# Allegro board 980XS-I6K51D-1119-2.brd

Outline 581.66 x 429.26 mm; copper layers: TOP, L02_GND, L03_DPS, L04_GND, L05_DPS, L06_GND, L07_DPS, L08_GND, L09_DPS, L10_GND, L11_DPS, L12_GND, L13_SIGNAL, L14_GND, L15_SIGNAL, L16_GND, L17_SIGNAL, L18_GND, L19_SIGNAL, L20_GND, L21_SIGNAL, L22_GND, L23_SIGNAL, L24_GND, L25_SIGNAL, L26_GND, L27_SIGNAL, L28_GND, L29_SIGNAL, L30_GND, L31_SIGNAL, L32_GND, L33_SIGNAL, L34_GND, L35_DPS, L36_UDB, L37_GND, BOTTOM. Coordinates in mm from the lower left corner of the outline.
Outline path: 0,429.26 206.45,429.26 arc(217.17,423.61) 227.89,429.26 353.77,429.26 arc(364.49,423.61) 375.21,429.26 581.66,429.26 581.66,0 301.55,0 arc(290.83,5.65) 280.11,0 0,0 0,429.26

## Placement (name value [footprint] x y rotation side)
BD5  BD120-1.5A-S4-MU  [FB0402]  543.47 239.79 270 bottom
BD9  BD120-1.5A-S4-MU  [FB0402]  224.66 243.83 270 bottom
BD21  BD120-1.5A-S4-MU  [FB0402]  222.95 232.36 0 bottom
BD1721  BD120-1.5A-S4-MU  [FB0402]  543.47 226.84 270 bottom
BD1722  BD120-1.5A-S4-MU  [FB0402]  543.09 213.5 270 bottom
BD1723  BD120-1.5A-S4-MU  [FB0402]  543.09 199.41 270 bottom
BD1728  BD120-1.5A-S4-MU  [FB0402]  245.15 273.73 180 bottom
BDB5  BD120-1.5A-S4-MU  [FB0402]  232.36 264.33 270 bottom
BDB6  BD120-1.5A-S4-MU  [FB0402]  220.55 264.33 270 bottom
BDB7  BD120-1.5A-S4-MU  [FB0402]  211.03 234.89 0 bottom
BDB8  BD120-1.5A-S4-MU  [FB0402]  211.03 246.46 0 bottom
BGA293-9X7-P0.4  REF-CODE-SOCKET  [SOCKET_CODE]  284.21 469.34 0 top
C262  0.1U-16-X7S-S2-MU  [C0201]  224.41 232.06 270 bottom
C264  NC/10U-16-X7R-S8-SS  [C0805]  243.28 276.07 0 bottom
C267  33P-50-N-S2-MU  [C0201]  236.23 224.18 270 bottom
C268  33P-50-N-S2-MU  [C0201]  235.23 224.18 270 bottom
C271  12P-50-N-S4-MU  [C0402]  240.52 270.61 90 bottom
C272  12P-50-N-S4-MU  [C0402]  240.52 272.63 270 bottom
C278  1U-10-X7S-S4-TDK  [C0402]  232.87 293.11 0 bottom
C279  1U-10-X7S-S4-TDK  [C0402]  232.87 291.92 0 bottom
C280  0.1U-16-X-S4-MU  [C0402]  232.87 290.72 0 bottom
C281  0.1U-16-X-S4-MU  [C0402]  232.87 289.53 0 bottom
C282  1U-10-X7S-S4-TDK  [C0402]  238.7 286.48 270 bottom
C283  0.1U-16-X-S4-MU  [C0402]  237.54 286.48 270 bottom
C284  1U-10-X7S-S4-TDK  [C0402]  237.62 297.85 90 bottom
C285  0.1U-16-X-S4-MU  [C0402]  238.81 297.85 90 bottom
C286  0.1U-16-X-S4-MU  [C0402]  233.82 297.35 180 bottom
C288  1000P-50-X7R-S2-MU  [C0201]  233.49 295.57 270 bottom
C289  0.1U-16-X-S4-MU  [C0402]  231.21 294.81 270 bottom
C290  NC/0.1U-16-X7R-S4-TY  [C0402]  224.35 296.03 180 bottom
C298  0.1U-16-X7S-S2-MU  [C0201]  222.95 292.65 90 bottom
C299  0.1U-16-X7S-S2-MU  [C0201]  220.02 296.97 180 bottom
C300  0.1U-16-X-S4-MU  [C0402]  220.67 290.87 270 bottom
C301  1U-10-X7S-S4-TDK  [C0402]  219.51 290.87 270 bottom
C302  10P-50-N-S2-MU  [C0201]  229.27 260.38 270 bottom
C309  10P-50-N-S2-MU  [C0201]  241.08 260.38 270 bottom
C310  10P-50-N-S2-MU  [C0201]  241.08 261.68 90 bottom
C318  10P-50-N-S2-MU  [C0201]  241.08 263.42 270 bottom
C320  10P-50-N-S2-MU  [C0201]  229.27 261.68 90 bottom
C332  2.2U-16-X7R-S6-TY  [C0603]  109.1 226.65 270 bottom
C333  0.1U-16-X-S4-MU  [C0402]  107.7 226.83 270 bottom
C334  10U-16-X7R-S8-SS  [C0805]  100.08 226.53 90 bottom
C335  0.1U-16-X-S4-MU  [C0402]  101.74 226.35 90 bottom
C336  4.7U-25-X7R-S8-TY  [C0805]  87.58 240.29 270 bottom
C337  0.1U-16-X-S4-MU  [C0402]  87.6 237.74 180 bottom
C338  4.7U-25-X7R-S8-TY  [C0805]  106 240.29 270 bottom
C339  0.1U-16-X-S4-MU  [C0402]  106.03 237.74 180 bottom
C400  2.2U-10-X-S4-MU  [C0402]  540.94 239.82 90 bottom
C401  0.1U-16-X-S4-MU  [C0402]  542.2 239.82 90 bottom
C402  4.7U-6.3-X-S4-MU  [C0402]  523.51 152.12 0 bottom
C403  22U-16-X5R-SA-SS  [C1206]  520.12 149.58 90 bottom
C404  10U-25-X-S6-MU  [C0603]  519.86 146.58 180 bottom
C405  1U-10-X7S-S4-TDK  [C0402]  520.37 145.26 180 bottom
C406  0.1U-16-X-S4-MU  [C0402]  90.42 287.53 180 bottom
C407  2.2U-10-X-S4-MU  [C0402]  82.6 288.09 270 bottom
C408  0.1U-16-X-S4-MU  [C0402]  83.74 288.09 270 bottom
C409  0.1U-16-X-S4-MU  [C0402]  73.71 296.14 0 bottom
C410  0.1U-16-X-S4-MU  [C0402]  508.66 225.73 270 bottom
C411  0.1U-16-X-S4-MU  [C0402]  498.63 233.78 0 bottom
C412  2.2U-10-X-S4-MU  [C0402]  507.51 225.73 270 bottom
C413  0.1U-16-X-S4-MU  [C0402]  515.33 225.16 180 bottom
C415  0.1U-16-X-S4-MU  [C0402]  90.42 273.81 180 bottom
C416  2.2U-10-X-S4-MU  [C0402]  82.6 274.38 270 bottom
C417  0.1U-16-X-S4-MU  [C0402]  73.71 282.43 0 bottom
C475  4.7U-6.3-X-S4-MU  [C0402]  256.72 272.09 270 bottom
C476  1U-10-X7S-S4-TDK  [C0402]  249.86 275.23 90 bottom
C477  10U-25-X-S6-MU  [C0603]  251.18 275.74 90 bottom
C478  22U-16-X5R-SA-SS  [C1206]  254.18 275.49 0 bottom
C894  0.1U-16-X-S4-MU  [C0402]  542.2 226.87 90 bottom
C895  2.2U-10-X-S4-MU  [C0402]  540.94 226.87 90 bottom
C910  0.1U-16-X-S4-MU  [C0402]  83.74 274.38 270 bottom
C922  0.1U-16-X-S4-MU  [C0402]  232.36 262.2 270 bottom
C923  0.1U-16-X-S4-MU  [C0402]  220.55 262.2 270 bottom
C924  10P-50-N-S2-MU  [C0201]  229.27 263.42 270 bottom
C955  0.1U-16-X-S4-MU  [C0402]  90.42 260.1 180 bottom
C956  2.2U-10-X-S4-MU  [C0402]  82.6 260.66 270 bottom
C957  0.1U-16-X-S4-MU  [C0402]  73.71 268.71 0 bottom
C958  0.1U-16-X-S4-MU  [C0402]  83.74 260.66 270 bottom
C983  0.1U-16-X-S4-MU  [C0402]  541.82 213.53 90 bottom
C984  2.2U-10-X-S4-MU  [C0402]  540.55 213.53 90 bottom
C985  0.1U-16-X-S4-MU  [C0402]  541.82 199.44 90 bottom
C986  2.2U-10-X-S4-MU  [C0402]  540.55 199.44 90 bottom
C1074  0.1U-16-X7S-S2-MU  [C0201_MINI]  243.6 273.98 90 bottom
C1082  0.1U-16-X-S4-MU  [C0402]  508.66 207.57 270 bottom
C1083  0.1U-16-X-S4-MU  [C0402]  248.15 224.79 0 bottom
C1085  2.2U-10-X-S4-MU  [C0402]  498.63 215.62 0 bottom
C1086  10P-50-N-S2-MU  [C0201]  214.98 255.18 0 bottom
C1087  10P-50-N-S2-MU  [C0201]  213.69 255.18 180 bottom
C1088  10P-50-N-S2-MU  [C0201]  211.94 255.18 0 bottom
C1089  0.1U-16-X-S4-MU  [C0402]  213.16 234.89 0 bottom
C1090  0.1U-16-X-S4-MU  [C0402]  213.16 246.46 0 bottom
C1091  10P-50-N-S2-MU  [C0201]  213.69 243.61 180 bottom
C1093  10P-50-N-S2-MU  [C0201]  214.98 243.61 0 bottom
CA1  0.1U-16-X-S4-MU  [C0402]  205.72 237.49 0 bottom
CA2  10U-25-X7R-SA  [C1206]  205.72 240.03 0 bottom
CA7  10U-25-X7R-SA  [C1206]  245.12 285.5 0 bottom
CA8  0.1U-16-X-S4-MU  [C0402]  245.12 283.46 0 bottom
CA19  470U-25-E-S10.4X10.4  [EC_10P3X10_S]  189.66 230.89 90 bottom
CA20  10U-25-X7R-SA  [C1206]  216.67 285.5 0 bottom
CA21  0.1U-16-X-S4-MU  [C0402]  216.67 283.46 0 bottom
CA22  10U-25-X7R-SA  [C1206]  222.76 281.43 0 bottom
CA23  0.1U-16-X-S4-MU  [C0402]  222.76 279.4 0 bottom
CA24  10U-25-X7R-SA  [C1206]  216.67 281.43 0 bottom
CA25  0.1U-16-X-S4-MU  [C0402]  216.67 279.4 0 bottom
CA26  10U-25-X7R-SA  [C1206]  235.18 281.43 0 bottom
CA27  0.1U-16-X-S4-MU  [C0402]  235.18 279.4 0 bottom
CA34  10U-25-X7R-SA  [C1206]  245.12 281.43 0 bottom
CA35  0.1U-16-X-S4-MU  [C0402]  245.12 279.4 0 bottom
CA36  0.1U-16-X-S4-MU  [C0402]  228.85 279.4 0 bottom
CA37  10U-25-X7R-SA  [C1206]  228.85 281.43 0 bottom
CA38  10U-25-X7R-SA  [C1206]  188.01 283.69 0 top
CA39  0.1U-16-X-S4-MU  [C0402]  206.26 242.54 0 top
CB1  0.1U-25-X-S6  [C0603]  416.81 133.35 0 bottom
CB2  10U-25-X7R-SA  [C1206]  416.81 130.81 0 bottom
CB3  0.1U-25-X-S6  [C0603]  560.07 133.35 0 bottom
CB4  10U-25-X7R-SA  [C1206]  560.07 130.81 0 bottom
CB5  0.1U-25-X-S6  [C0603]  560.07 295.91 180 bottom
CB6  10U-25-X7R-SA  [C1206]  560.07 298.45 180 bottom
CB7  0.1U-25-X-S6  [C0603]  424.16 290.83 180 bottom
CB8  10U-25-X7R-SA  [C1206]  424.16 293.37 180 bottom
CB9  0.1U-25-X-S6  [C0603]  164.85 133.35 0 bottom
CB10  10U-25-X7R-SA  [C1206]  164.85 130.81 0 bottom
CB11  0.1U-25-X-S6  [C0603]  157.46 290.83 180 bottom
CB12  10U-25-X7R-SA  [C1206]  157.46 293.37 180 bottom
CB13  0.1U-25-X-S6  [C0603]  21.59 133.35 0 bottom
CB14  10U-25-X7R-SA  [C1206]  21.59 130.81 0 bottom
CB15  0.1U-25-X-S6  [C0603]  21.59 295.91 180 bottom
CB16  10U-25-X7R-SA  [C1206]  21.59 298.45 180 bottom
CC1  0.1U-16-X7S-S2-MU  [C0201_MINI]  230.19 246.91 180 bottom
CC2  0.1U-16-X7S-S2-MU  [C0201_MINI]  230.5 250.48 90 bottom
CC3  0.1U-16-X7S-S2-MU  [C0201_MINI]  228.87 245.61 180 bottom
CC4  0.1U-16-X7S-S2-MU  [C0201_MINI]  230.19 246.26 180 bottom
CC5  0.1U-16-X7S-S2-MU  [C0201_MINI]  231.16 246.56 90 bottom
CC6  0.1U-16-X7S-S2-MU  [C0201_MINI]  228.87 244.96 180 bottom
CC7  0.1U-16-X7S-S2-MU  [C0201_MINI]  232.14 244.96 0 bottom
CC8  0.1U-16-X7S-S2-MU  [C0201_MINI]  230.5 243.97 270 bottom
CC9  0.1U-16-X7S-S2-MU  [C0201_MINI]  231.16 243.97 270 bottom
CC12  0.1U-16-X7S-S2-MU  [C0201_MINI]  229.86 244.62 270 bottom
CC13  0.1U-16-X7S-S2-MU  [C0201_MINI]  228.24 241.05 180 bottom
CC14  0.1U-16-X7S-S2-MU  [C0201_MINI]  231.46 245.61 0 bottom
CC15  0.1U-16-X7S-S2-MU  [C0201_MINI]  230.19 245.61 180 bottom
CC16  0.1U-16-X7S-S2-MU  [C0201_MINI]  230.84 244.96 180 bottom
CC70  0.1U-16-X7S-S2-MU  [C0201_MINI]  232.46 242.67 270 bottom
CC71  0.1U-16-X7S-S2-MU  [C0201_MINI]  235.38 243 0 bottom
CC73  0.1U-16-X7S-S2-MU  [C0201_MINI]  227.91 242.68 90 bottom
CC84  0.1U-16-X7S-S2-MU  [C0201_MINI]  233.11 250.48 90 bottom
CC85  0.1U-16-X7S-S2-MU  [C0201_MINI]  231.15 250.48 90 bottom
CC86  0.1U-16-X7S-S2-MU  [C0201_MINI]  232.46 250.48 90 bottom
CC87  0.1U-16-X7S-S2-MU  [C0201_MINI]  232.14 246.26 180 bottom
CC88  0.1U-16-X7S-S2-MU  [C0201_MINI]  233.11 244 270 bottom
CC89  0.1U-16-X7S-S2-MU  [C0201_MINI]  227.91 244.66 270 bottom
CC90  0.1U-16-X7S-S2-MU  [C0201_MINI]  231.8 250.48 90 bottom
CC91  0.1U-16-X7S-S2-MU  [C0201_MINI]  234.06 243.65 0 bottom
CC92  0.1U-16-X7S-S2-MU  [C0201_MINI]  232.45 244 270 bottom
CC96  0.1U-16-X7S-S2-MU  [C0201_MINI]  231.51 247.56 180 bottom
CC101  0.1U-16-X7S-S2-MU  [C0201_MINI]  230.84 240.4 0 bottom
CC103  0.1U-16-X7S-S2-MU  [C0201_MINI]  231.81 242.02 90 bottom
CC105  0.1U-16-X7S-S2-MU  [C0201_MINI]  232.46 240.72 270 bottom
CC112  0.1U-16-X7S-S2-MU  [C0201_MINI]  235.06 250.48 90 bottom
CC130  0.1U-16-X7S-S2-MU  [C0201_MINI]  228.24 241.7 180 bottom
CC182  0.1U-16-X7S-S2-MU  [C0201_MINI]  226.61 250.48 90 bottom
CC195  4.7U-25-X7R-S8-TY  [C0805]  187.38 280.77 0 top
CC202  0.1U-16-X7S-S2-MU  [C0201_MINI]  226.28 245.61 180 bottom
CC211  0.1U-16-X7S-S2-MU  [C0201_MINI]  230.5 242.02 90 bottom
CC212  0.1U-16-X7S-S2-MU  [C0201_MINI]  229.53 241.06 180 bottom
CC213  0.1U-16-X7S-S2-MU  [C0201_MINI]  231.16 242.02 90 bottom
CC214  0.1U-16-X7S-S2-MU  [C0201_MINI]  192.95 287.28 90 top
CC215  0.1U-16-X7S-S2-MU  [C0201_MINI]  231.81 239.42 90 bottom
CC216  0.1U-16-X7S-S2-MU  [C0201_MINI]  228.56 238.78 270 bottom
CC217  0.1U-16-X7S-S2-MU  [C0201_MINI]  194.35 287.28 90 top
CC218  0.1U-16-X7S-S2-MU  [C0201_MINI]  195.75 287.28 90 top
CC219  0.1U-16-X7S-S2-MU  [C0201_MINI]  197.15 287.28 90 top
CC220  0.1U-16-X7S-S2-MU  [C0201_MINI]  198.56 287.28 90 top
CON1  MS-PWR-CONN-30P-V3-SI6D70  [CONN_15X2_100MIL_PH_MS_V2]  24.74 150.36 90 top
CSDPS303  V93K_CSDPS_DPS32  [PG_VG93K_PF_DPS32_G1D303]  327.66 46.99 0 top
CSDPS307  V93K_CSDPS_DPS32  [PG_VG93K_PF_DPS32_G1D307]  401.32 46.99 0 top
CSDPS310  V93K_CSDPS_DPS32  [PG_VG93K_PF_DPS32_G2D310]  401.32 361.95 0 top
CSDPS314  V93K_CSDPS_DPS32  [PG_VG93K_PF_DPS32_G2D314]  327.66 361.95 0 top
CSDPS319  V93K_CSDPS_DPS32  [PG_VG93K_PF_DPS32_G3D319]  180.34 46.99 0 top
CSDPS323  V93K_CSDPS_DPS32  [PG_VG93K_PF_DPS32_G3D323]  254 46.99 0 top
CSDPS426  V93K_CSDPS  [PG_VG93K_PF_DPS32_G8D426]  254 361.95 0 top
CSDPS430  V93K_CSDPS  [PG_VG93K_PF_DPS32_G8D430]  180.34 361.95 0 top
D101  V93K_CH  [PG_VG93K_F_G1D101]  327.66 97.79 0 top
D102  V93K_CH  [PG_VG93K_F_G1D102]  327.66 77.47 0 top
D103  V93K_CH  [PG_VG93K_F_G1D103]  327.66 57.15 0 top
D104  V93K_CH  [PG_VG93K_F_G1D104]  327.66 36.83 0 top
D105  V93K_CH  [PG_VG93K_F_G1D105]  401.32 97.79 0 top
D106  V93K_CH  [PG_VG93K_F_G1D106]  401.32 77.47 0 top
D107  V93K_CH  [PG_VG93K_F_G1D107]  401.32 57.15 0 top
D108  V93K_CH  [PG_VG93K_F_G1D108]  401.32 36.83 0 top
D109  V93K_CH  [PG_VG93K_F_G2D109]  401.32 331.47 0 top
D110  V93K_CH  [PG_VG93K_F_G2D110]  401.32 351.79 0 top
D111  V93K_CH  [PG_VG93K_F_G2D111]  401.32 372.11 0 top
D112  V93K_CH  [PG_VG93K_F_G2D112]  401.32 392.43 0 top
D113  V93K_CH  [PG_VG93K_F_G2D113]  327.66 331.47 0 top
D114  V93K_CH  [PG_VG93K_F_G2D114]  327.66 351.79 0 top
D115  V93K_CH  [PG_VG93K_F_G2D115]  327.66 372.11 0 top
D116  V93K_CH  [PG_VG93K_F_G2D116]  327.66 392.43 0 top
D117  V93K_CH  [PG_VG93K_F_G3D117]  180.34 97.79 0 top
D118  V93K_CH  [PG_VG93K_F_G3D118]  180.34 77.47 0 top
D119  V93K_CH  [PG_VG93K_F_G3D119]  180.34 57.15 0 top
D120  V93K_CH  [PG_VG93K_F_G3D120]  180.34 36.83 0 top
D121  V93K_CH  [PG_VG93K_F_G3D121]  254 97.79 0 top
D122  V93K_CH  [PG_VG93K_F_G3D122]  254 77.47 0 top
D123  V93K_CH  [PG_VG93K_F_G3D123]  254 57.15 0 top
D124  V93K_CH  [PG_VG93K_F_G3D124]  254 36.83 0 top
D125  V93K_CH  [PG_VG93K_F_G4D125]  33.02 97.79 0 top
D126  V93K_CH  [PG_VG93K_F_G4D126]  33.02 77.47 0 top
D127  V93K_CH  [PG_VG93K_F_G4D127]  33.02 57.15 0 top
D128  V93K_CH  [PG_VG93K_F_G4D128]  33.02 36.83 0 top
D129  V93K_CH  [PG_VG93K_F_G4D129]  106.68 97.79 0 top
D130  V93K_CH  [PG_VG93K_F_G4D130]  106.68 77.47 0 top
D131  V93K_CH  [PG_VG93K_F_G4D131]  106.68 57.15 0 top
D132  V93K_CH  [PG_VG93K_F_G4D132]  106.68 36.83 0 top
D201  V93K_CH  [PG_VG93K_F_G5D201]  474.98 97.79 0 top
D202  V93K_CH  [PG_VG93K_F_G5D202]  474.98 77.47 0 top
D203  V93K_CH  [PG_VG93K_F_G5D203]  474.98 57.15 0 top
D204  V93K_CH  [PG_VG93K_F_G5D204]  474.98 36.83 0 top
D205  V93K_CH  [PG_VG93K_F_G5D205]  548.64 97.79 0 top
D206  V93K_CH  [PG_VG93K_F_G5D206]  548.64 77.47 0 top
D207  V93K_CH  [PG_VG93K_F_G5D207]  548.64 57.15 0 top
D208  V93K_CH  [PG_VG93K_F_G5D208]  548.64 36.83 0 top
D209  V93K_CH  [PG_VG93K_F_G6D209]  548.64 331.47 0 top
D210  V93K_CH  [PG_VG93K_F_G6D210]  548.64 351.79 0 top
D211  V93K_CH  [PG_VG93K_F_G6D211]  548.64 372.11 0 top
D212  V93K_CH  [PG_VG93K_F_G6D212]  548.64 392.43 0 top
D213  V93K_CH  [PG_VG93K_F_G6D213]  474.98 331.47 0 top
D214  V93K_CH  [PG_VG93K_F_G6D214]  474.98 351.79 0 top
D215  V93K_CH  [PG_VG93K_F_G6D215]  474.98 372.11 0 top
D216  V93K_CH  [PG_VG93K_F_G6D216]  474.98 392.43 0 top
D217  V93K_CH  [PG_VG93K_F_G7D217]  106.68 331.47 0 top
D218  V93K_CH  [PG_VG93K_F_G7D218]  106.68 351.79 0 top
D219  V93K_CH  [PG_VG93K_F_G7D219]  106.68 372.11 0 top
D220  V93K_CH  [PG_VG93K_F_G7D220]  106.68 392.43 0 top
D221  V93K_CH  [PG_VG93K_F_G7D221]  33.02 331.47 0 top
D222  V93K_CH  [PG_VG93K_F_G7D222]  33.02 351.79 0 top
D223  V93K_CH  [PG_VG93K_F_G7D223]  33.02 372.11 0 top
D224  V93K_CH  [PG_VG93K_F_G7D224]  33.02 392.43 0 top
D225  V93K_CH_ND  [PG_VG93K_F_G8D225_ND]  254 331.47 0 top
D226/D626  V93K_PS1600 HD  [PG_VG93K_F_HSM_G8D226_626_ND]  254 351.79 0 top
D227  V93K_CH  [PG_VG93K_F_G8D227]  254 372.11 0 top
D228  V93K_CH  [PG_VG93K_F_G8D228]  254 392.43 0 top
D229  V93K_CH_ND  [PG_VG93K_F_G8D229_ND]  180.34 331.47 0 top
D230/D630  V93K_PS1600 HD  [PG_VG93K_F_HSM_G8D230_630_ND]  180.34 351.79 0 top
D231  V93K_CH  [PG_VG93K_F_G8D231]  180.34 372.11 0 top
D232  V93K_CH  [PG_VG93K_F_G8D232]  180.34 392.43 0 top
D325  V93K_CH  [PG_VG93K_F_G4D325]  33.02 87.63 0 top
D326  V93K_CH  [PG_VG93K_F_G4D326]  33.02 67.31 0 top
D327  V93K_CH  [PG_VG93K_F_G4D327]  33.02 46.99 0 top
D328  V93K_CH  [PG_VG93K_F_G4D328]  33.02 26.67 0 top
D329  V93K_CH  [PG_VG93K_F_G4D329]  106.68 87.63 0 top
D330  V93K_CH  [PG_VG93K_F_G4D330]  106.68 67.31 0 top
D331  V93K_CH  [PG_VG93K_F_G4D331]  106.68 46.99 0 top
D332  V93K_CH  [PG_VG93K_F_G4D332]  106.68 26.67 0 top
D409  V93K_CH  [PG_VG93K_F_G6D409]  548.64 341.63 0 top
D410  V93K_CH  [PG_VG93K_F_G6D410]  548.64 361.95 0 top
D411  V93K_CH  [PG_VG93K_F_G6D411]  548.64 382.27 0 top
D412  V93K_CH  [PG_VG93K_F_G6D412]  548.64 402.59 0 top
D413  V93K_CH  [PG_VG93K_F_G6D413]  474.98 341.63 0 top
D414  V93K_CH  [PG_VG93K_F_G6D414]  474.98 361.95 0 top
D415  V93K_CH  [PG_VG93K_F_G6D415]  474.98 382.27 0 top
D416  V93K_CH  [PG_VG93K_F_G6D416]  474.98 402.59 0 top
D417  V93K_CH  [PG_VG93K_F_G7D417]  106.68 341.63 0 top
D418  V93K_CH  [PG_VG93K_F_G7D418]  106.68 361.95 0 top
D419  V93K_CH  [PG_VG93K_F_G7D419]  106.68 382.27 0 top
D420  V93K_CH  [PG_VG93K_F_G7D420]  106.68 402.59 0 top
D421  V93K_CH  [PG_VG93K_F_G7D421]  33.02 341.63 0 top
D422  V93K_CH  [PG_VG93K_F_G7D422]  33.02 361.95 0 top
D423  V93K_CH  [PG_VG93K_F_G7D423]  33.02 382.27 0 top
D424  V93K_CH  [PG_VG93K_F_G7D424]  33.02 402.59 0 top
D425  V93K_CH_ND  [PG_VG93K_F_G8D425_ND]  254 341.63 0 top
D427  V93K_CH  [PG_VG93K_F_G8D427]  254 382.27 0 top
D428  V93K_CH  [PG_VG93K_F_G8D428]  254 402.59 0 top
D429  V93K_CH_ND  [PG_VG93K_F_G8D429_ND]  180.34 341.63 0 top
D431  V93K_CH  [PG_VG93K_F_G8D431]  180.34 382.27 0 top
D432  V93K_CH  [PG_VG93K_F_G8D432]  180.34 402.59 0 top
DPS1  V93K_DPS  [PG_VG93K_F_G1DPS1]  401.32 16.51 0 top
DPS2  V93K_DPS  [PG_VG93K_F_G2DPS2]  327.66 412.75 0 top
DPS3  V93K_DPS  [PG_VG93K_F_G3DPS3]  254 16.51 0 top
DPS8  V93K_DPS  [PG_VG93K_F_G8DPS8]  180.34 412.75 0 top
FD1  -  [FD_040_V2]  10.16 129.54 0 top
FD2  -  [FD_040_V2]  11.43 298.45 0 top
FD3  -  [FD_040_V2]  157.48 298.45 0 top
FD4  -  [FD_040_V2]  157.48 130.81 0 top
FD5  -  [FD_040_V2]  424.18 298.45 0 top
FD6  -  [FD_040_V2]  424.18 130.81 0 top
FD7  -  [FD_040_V2]  570.23 298.45 0 top
FD8  -  [FD_040_V2]  570.23 130.81 0 top
FD9  -  [FD_040_V2]  10.16 129.54 180 bottom
FD10  -  [FD_040_V2]  11.43 298.45 180 bottom
FD11  -  [FD_040_V2]  157.48 298.45 180 bottom
FD12  -  [FD_040_V2]  157.48 130.81 180 bottom
FD13  -  [FD_040_V2]  424.18 298.45 180 bottom
FD14  -  [FD_040_V2]  424.18 130.81 180 bottom
FD15  -  [FD_040_V2]  570.23 298.45 180 bottom
FD16  -  [FD_040_V2]  570.23 130.81 180 bottom
H1  M3-HOLE  [M3_NPTH169]  158.75 241.3 0 top
H2  M3-HOLE  [M3_NPTH169]  158.75 187.96 0 top
H3  M3-HOLE  [M3_NPTH169]  422.91 241.3 0 top
H4  M3-HOLE  [M3_NPTH169]  422.91 187.96 0 top
J1  HDR-2X1-M  [JP_2P_100]  10.78 152.9 180 top
J2  HDR-2X1-M  [JP_2P_100]  14.16 152.9 180 top
JG261002WW011  REF-CODE-SOCKET  [SOCKET_CODE]  284.82 469.34 0 top
JP1  A2001WV0-4PS_V2  [CONN_S4X1_2MM_JWT]  100.37 260.08 90 top
K2  UA2-5NJ-A-V3  [RL_NECUA2_5V_V3]  119.04 248.1 90 bottom
K3  UA2-5NJ-A-V3  [RL_NECUA2_5V_V3]  112.69 248.1 90 bottom
K4  UA2-5NJ-A-V3  [RL_NECUA2_5V_V3]  106.34 248.1 90 bottom
K5  UA2-5NJ-A-V3  [RL_NECUA2_5V_V3]  99.99 248.1 90 bottom
K6  UA2-5NJ-A-V3  [RL_NECUA2_5V_V3]  93.64 248.1 90 bottom
K7  UA2-5NJ-A-V3  [RL_NECUA2_5V_V3]  87.29 248.1 90 bottom
K29  G6K-2F-Y-5V-A  [RL_G6K2F-Y_5V_OMRON]  231.89 271.62 0 bottom
K32  G6K-2F-Y-5V-A  [RL_G6K2F-Y_5V_OMRON]  235.73 231.79 270 bottom
K34  G6K-2P-Y5VDC-A  [RL_OMRONG6K2PY_5V]  166.88 269.24 90 bottom
K96  EC2-5NJ  [RL_NECEC2_10P_5V]  203.76 229.39 0 bottom
K109  G6K-2P-Y5VDC-A  [RL_OMRONG6K2PY_5V]  166.88 293.62 90 bottom
K110  G6K-2P-Y5VDC-A  [RL_OMRONG6K2PY_5V]  176.53 293.62 90 bottom
LDB1  LDG-2-S8  [LED_0805]  40.96 298.45 0 top
LOGO1  LOGO_SR_SigmaStar  [LOGO_SR_SIGMASTAR]  29.16 434.98 0 top
LOGO2  -  [LOGO_KT_KSMT]  81.21 434.37 0 top
LRB1  330-1-S6  [R0603]  42.89 298.45 180 bottom
MBD1  BD120-1.5A-S4-MU  [FB0402]  222.95 294.3 270 bottom
MK1  AQY221R2MY-V2  [RL_AQY221R2MY_5V_V2]  225.87 288.33 180 bottom
MK2  AQY221R2MY-V2  [RL_AQY221R2MY_5V_V2]  225.87 293.67 180 bottom
MK3  AQY221R2MY-V2  [RL_AQY221R2MY_5V_V2]  225.87 285.79 180 bottom
MK4  AQY221R2MY-V2  [RL_AQY221R2MY_5V_V2]  225.87 291 180 bottom
MR1  1M-1-S4  [R0402_UNBGA_V2]  236.22 286.48 270 bottom
MR2  1K-0.01-S4  [R0402_UNBGA_V2]  235.91 297.35 180 bottom
MR3  1K-0.01-S4  [R0402_UNBGA_V2]  233.82 298.37 180 bottom
MR4  1K-0.01-S4  [R0402_UNBGA_V2]  233.82 299.38 180 bottom
MR5  1K-0.01-S4  [R0402_UNBGA_V2]  235.91 299.38 0 bottom
MR6  1K-0.01-S4  [R0402_UNBGA_V2]  235.91 298.37 0 bottom
MR7  332K-1-S4  [R0402_UNBGA_V2]  235.21 285.63 90 bottom
MR8  1K-0.01-S4  [R0402_UNBGA_V2]  224.35 299.38 180 bottom
MR9  499-0.1-S4  [R0402]  224.35 298.27 180 bottom
MR10  0-5-S4  [R0402]  224.35 297.15 0 bottom
MR11  750-1-S4  [R0402]  229.3 288.97 180 bottom
MR12  360-1-S6  [R0603]  229.68 287.7 180 bottom
MR13  750-1-S4  [R0402]  229.3 294.3 180 bottom
MR14  1.2K-1-S4  [R0402]  229.05 286.43 0 bottom
MR15  360-1-S6  [R0603]  229.68 293.03 180 bottom
MR16  750-1-S4  [R0402]  229.3 291.64 180 bottom
MR17  360-1-S6  [R0603]  229.68 290.37 180 bottom
MR18  11K-0.1-S4  [R0402]  221.81 290.87 270 bottom
MR19  1K-0.01-S4  [R0402_UNBGA_V2]  222.95 290.87 90 bottom
MU1  KSMT002-0.15A-A-SC70-5  [SC70_5P]  233.15 287.63 90 bottom
MU2  KSMT004-SO8  [SO8_244X127MM]  238.06 292.02 90 bottom
MU3  KSMT003-MSOP8  [SO8_172X0P65MM]  228.92 297.48 180 bottom
MU4  MAX6070AAUT30+T-SOT23  [SOT23_6P_0P95X2P7MM_H1P45MM]  220.67 294.3 0 bottom
NOREF  -  []  331.64 183.61 0 top
NOREF#2  -  []  311.26 247.56 0 top
NOREF#3  -  []  65.76 265.88 0 top
NOREF#4  -  []  468.26 233.65 0 top
NOREF#5  -  []  213.86 192.91 90 top
NOREF#6  -  []  274.82 284.84 90 top
NOREF#7  -  []  84.1 291.32 0 top
NOREF#8  -  []  311.03 245.37 0 top
NOREF#9  -  []  15.24 484.4 0 top
NOREF#10  -  []  274.61 299.77 0 top
NOREF#11  -  []  568.42 164.1 0 top
NOREF#12  -  []  230.55 134.62 90 top
NOREF#13  -  []  235.48 298.37 0 top
NOREF#14  -  []  253.1 240.02 0 top
NOREF#15  -  []  248.81 483.75 90 top
NOREF#16  -  []  256.21 192.91 90 top
NOREF#17  -  []  228.17 137.2 90 top
NOREF#18  -  []  414.35 467.68 0 top
NOREF#19  -  []  271.78 183.92 90 top
NOREF#20  -  []  318.39 483.75 90 top
NOREF#21  -  []  95.99 154.45 0 top
NOREF#22  -  []  466.83 221.76 0 top
NOREF#23  -  []  94.33 260.42 0 top
NOREF#24  -  []  210.61 252.27 0 top
NOREF#25  -  []  107.85 162.3 90 top
NOREF#26  -  []  130.62 484.32 0 top
NOREF#27  -  []  41.44 255.11 0 top
NOREF#28  -  []  294.38 194.86 0 top
NOREF#29  -  []  99.29 252.5 0 top
NOREF#30  -  []  144.05 484.32 0 top
NOREF#31  -  []  233.07 254.55 0 top
NOREF#32  -  []  231.89 186.26 0 top
NOREF#33  -  []  322.54 140.92 0 top
NOREF#34  -  []  116.42 127.72 90 top
NOREF#35  -  []  296.91 181.35 90 top
NOREF#36  -  []  222.45 171.5 0 top
NOREF#37  -  []  255.01 182 0 top
NOREF#38  -  []  228.53 184.61 90 top
NOREF#39  -  []  104.48 236.15 90 top
NOREF#40  -  []  226.71 245.85 0 top
NOREF#41  -  []  548.24 225.79 0 top
NOREF#42  -  []  301.84 264.24 0 top
NOREF#43  -  []  341.29 297.9 0 top
NOREF#44  -  []  269.28 181.06 0 top
NOREF#45  -  []  239.47 258.45 90 top
NOREF#46  -  []  269.96 181.3 0 top
NOREF#47  -  []  534.61 218.68 0 top
NOREF#48  -  []  115.04 186.2 0 top
NOREF#49  -  []  77.67 274.95 0 top
NOREF#50  -  []  397.17 484.4 0 top
NOREF#51  -  []  363.96 287.7 90 top
NOREF#52  -  []  254.36 181.55 0 top
NOREF#53  -  []  535.13 208.56 90 top
NOREF#54  -  []  359.73 246.59 0 top
NOREF#55  -  []  10.78 2.28 90 top
NOREF#56  -  []  355.81 242.28 90 top
NOREF#57  -  []  311.78 183.92 90 top
NOREF#58  -  []  85.29 188.85 90 top
NOREF#59  -  []  234.61 297.98 90 top
NOREF#60  -  []  153.33 483.84 90 top
NOREF#61  -  []  475.32 173.92 90 top
NOREF#62  -  []  103.28 173.3 0 top
NOREF#63  -  []  233.63 146.07 0 top
NOREF#64  -  []  351.8 250.23 90 top
NOREF#65  -  []  333.1 191.59 0 top
NOREF#66  -  []  310.82 240.82 90 top
NOREF#67  -  []  315.81 182.28 90 top
NOREF#68  -  []  253.22 238.82 0 top
NOREF#69  -  []  490.28 253.51 0 top
NOREF#70  -  []  470.13 161.06 0 top
NOREF#71  -  []  315.79 484.4 0 top
NOREF#72  -  []  294.66 241.23 0 top
NOREF#73  -  []  351.48 186.67 90 top
NOREF#74  -  []  549.44 222.35 90 top
NOREF#75  -  []  253.22 178.82 0 top
NOREF#76  -  []  213.66 243.2 0 top
NOREF#77  -  []  334.31 253.56 0 top
NOREF#78  -  []  509.92 229.28 0 top
NOREF#79  -  []  87.81 196.06 90 top
NOREF#80  -  []  302.95 292.35 90 top
NOREF#81  -  []  273.17 484.08 0 top
NOREF#82  -  []  347.56 144.79 90 top
NOREF#83  -  []  474.48 201.65 0 top
NOREF#84  -  []  257.83 252.37 0 top
NOREF#85  -  []  321.4 484.4 0 top
NOREF#86  -  []  458.53 253.51 0 top
NOREF#87  -  []  228.95 262.82 90 top
NOREF#88  -  []  226.85 250.05 0 top
NOREF#89  -  []  547.86 208.27 0 top
NOREF#90  -  []  312.23 230.19 90 top
NOREF#91  -  []  533.93 207.81 0 top
NOREF#92  -  []  267.57 245.37 90 top
NOREF#93  -  []  236.23 163.88 90 top
NOREF#94  -  []  320.83 157.63 90 top
NOREF#95  -  []  331.64 242.3 90 top
NOREF#96  -  []  493.92 238.07 0 top
NOREF#97  -  []  356.7 297.74 0 top
NOREF#98  -  []  347.99 241.05 0 top
NOREF#99  -  []  246.51 484.08 0 top
NOREF#100  -  []  229.61 185.05 0 top
NOREF#101  -  []  309.69 136.26 90 top
NOREF#102  -  []  359.59 484.08 0 top
NOREF#103  -  []  215.83 199.63 0 top
NOREF#104  -  []  352.21 244.43 0 top
NOREF#105  -  []  270.16 184.72 90 top
NOREF#106  -  []  302.49 297.25 90 top
NOREF#107  -  []  476.48 192.81 0 top
NOREF#108  -  []  311.94 187.8 0 top
NOREF#109  -  []  313.81 183.65 0 top
NOREF#110  -  []  243.4 484.4 0 top
NOREF#111  -  []  227.25 174.3 90 top
NOREF#112  -  []  493.02 142.49 0 top
NOREF#113  -  []  242 484.4 0 top
NOREF#114  -  []  310.62 187.15 0 top
NOREF#115  -  []  275.12 299.77 90 top
NOREF#116  -  []  271.26 483.75 90 top
NOREF#117  -  []  472.43 160.26 0 top
NOREF#118  -  []  63.76 272.89 0 top
NOREF#119  -  []  38.89 266.66 0 top
NOREF#120  -  []  348.03 292.21 0 top
NOREF#121  -  []  354.44 138.77 0 top
NOREF#122  -  []  269.33 210.27 0 top
NOREF#123  -  []  275.13 243 0 top
NOREF#124  -  []  335.58 254.22 90 top
NOREF#125  -  []  234.61 299.77 0 top
NOREF#126  -  []  508.11 227.95 90 top
NOREF#127  -  []  312.21 184.43 0 top
NOREF#128  -  []  212.66 253.56 90 top
NOREF#129  -  []  213.39 255.18 0 top
NOREF#130  -  []  353.1 243.75 90 top
NOREF#131  -  []  289.13 484.4 0 top
NOREF#132  -  []  308.57 483.75 90 top
NOREF#133  -  []  252.54 194.22 90 top
NOREF#134  -  []  18.34 484.08 0 top
NOREF#135  -  []  481.73 158.26 0 top
NOREF#136  -  []  124.28 204.4 90 top
NOREF#137  -  []  227.71 249.57 90 top
NOREF#138  -  []  310.16 245.37 90 top
NOREF#139  -  []  397.47 484.08 0 top
NOREF#140  -  []  369.83 222.63 90 top
NOREF#141  -  []  352.21 184.43 0 top
NOREF#142  -  []  251.16 180.15 0 top
NOREF#143  -  []  255.09 206.49 0 top
NOREF#144  -  []  526.78 484.4 0 top
NOREF#145  -  []  213.32 14.14 90 top
NOREF#146  -  []  233.56 189.57 90 top
NOREF#147  -  []  303.95 173.34 90 top
NOREF#148  -  []  263.95 234.46 90 top
NOREF#149  -  []  273.07 183.95 90 top
NOREF#150  -  []  347.25 174.3 90 top
NOREF#151  -  []  80.69 273.73 90 top
NOREF#152  -  []  284.92 484.4 0 top
NOREF#153  -  []  351.94 187.8 0 top
NOREF#154  -  []  293.39 255.18 0 top
NOREF#155  -  []  351.48 246.66 90 top
NOREF#156  -  []  224.52 291.64 0 top
NOREF#157  -  []  269.61 245.05 0 top
NOREF#158  -  []  214.3 179.37 90 top
NOREF#159  -  []  335.01 242 0 top
NOREF#160  -  []  479.53 190.01 0 top
NOREF#161  -  []  476.48 224.56 0 top
NOREF#162  -  []  552.28 164.49 0 top
NOREF#163  -  []  303.09 233.82 0 top
NOREF#164  -  []  92.33 165.46 90 top
NOREF#165  -  []  250.42 484.4 0 top
NOREF#166  -  []  312.46 182.42 90 top
NOREF#167  -  []  343.09 174.94 0 top
NOREF#168  -  []  335.71 240.7 0 top
NOREF#169  -  []  235.48 297.35 0 top
NOREF#170  -  []  309.28 181.06 0 top
NOREF#171  -  []  273.3 208.63 90 top
NOREF#172  -  []  298.44 299.07 0 top
NOREF#173  -  []  311.81 239.17 90 top
NOREF#174  -  []  223.27 235.18 0 top
NOREF#175  -  []  398.87 484.08 0 top
NOREF#176  -  []  255.58 182.65 90 top
NOREF#177  -  []  122.64 214.75 90 top
NOREF#178  -  []  308.14 242.25 0 top
NOREF#179  -  []  312.26 181.11 90 top
NOREF#180  -  []  357.95 135.78 90 top
NOREF#181  -  []  234.49 242.93 90 top
NOREF#182  -  []  267.05 483.75 90 top
NOREF#183  -  []  473.2 197.18 90 top
NOREF#184  -  []  385.95 484.4 0 top
NOREF#185  -  []  354.12 463.08 90 top
NOREF#186  -  []  267.99 181.7 0 top
NOREF#187  -  []  215.58 254.86 90 top
NOREF#188  -  []  311.48 185.37 90 top
NOREF#189  -  []  458.65 168.12 90 top
NOREF#190  -  []  233.08 182.62 90 top
NOREF#191  -  []  108.69 217.95 0 top
NOREF#192  -  []  135.63 484.32 0 top
NOREF#193  -  []  123.08 202.51 0 top
NOREF#194  -  []  274.21 249.57 90 top
NOREF#195  -  []  487.59 201.13 90 top
NOREF#196  -  []  238.09 484.08 0 top
NOREF#197  -  []  254.42 189.74 90 top
NOREF#198  -  []  483.31 162.33 90 top
NOREF#199  -  []  254.63 484.4 0 top
NOREF#200  -  []  273.63 138.2 0 top
NOREF#201  -  []  333.1 251.59 0 top
NOREF#202  -  []  235.3 250.05 0 top
NOREF#203  -  []  460.48 221.76 0 top
NOREF#204  -  []  293.29 182.3 90 top
NOREF#205  -  []  271.89 186.26 0 top
NOREF#206  -  []  91.84 154.45 0 top
NOREF#207  -  []  543.98 154.6 0 top
NOREF#208  -  []  272.35 284.59 90 top
NOREF#209  -  []  228.93 208.11 0 top
NOREF#210  -  []  215.38 182.3 90 top
NOREF#211  -  []  451.08 256.31 0 top
NOREF#212  -  []  309.94 186.26 0 top
NOREF#213  -  []  408.7 484.08 0 top
NOREF#214  -  []  307.57 185.37 90 top
NOREF#215  -  []  263.92 299.38 0 top
NOREF#216  -  []  104.34 157.1 90 top
NOREF#217  -  []  226.41 254.4 90 top
NOREF#218  -  []  310.87 270.03 90 top
NOREF#219  -  []  310.5 241.77 90 top
NOREF#220  -  []  85.49 217.95 0 top
NOREF#221  -  []  83.29 186.2 0 top
NOREF#222  -  []  414.15 462.48 90 top
NOREF#223  -  []  391.94 463.08 90 top
NOREF#224  -  []  354.21 189.57 90 top
NOREF#225  -  []  118.85 483.84 90 top
NOREF#226  -  []  225.33 133.69 0 top
NOREF#227  -  []  351.15 181.77 90 top
NOREF#228  -  []  312.04 190.05 0 top
NOREF#229  -  []  135.81 484.08 0 top
NOREF#230  -  []  32.37 484.08 0 top
NOREF#231  -  []  199.18 286.37 90 top
NOREF#232  -  []  370.92 462.48 90 top
NOREF#233  -  []  268.49 136.9 0 top
NOREF#234  -  []  347.75 172.44 90 top
NOREF#235  -  []  451.08 192.81 0 top
NOREF#236  -  []  333.99 242.3 90 top
NOREF#237  -  []  402.74 463.08 90 top
NOREF#238  -  []  231.27 185.2 0 top
NOREF#239  -  []  84.1 262.43 0 top
NOREF#240  -  []  80.24 157.25 0 top
NOREF#241  -  []  348.25 173.12 0 top
NOREF#242  -  []  282.33 173.13 90 top
NOREF#243  -  []  295.71 252.27 0 top
NOREF#244  -  []  258.63 483.75 90 top
NOREF#245  -  []  355.91 164.78 0 top
NOREF#246  -  []  107.94 251.7 0 top
NOREF#247  -  []  271.16 181.77 90 top
NOREF#248  -  []  97.42 166.34 0 top
NOREF#249  -  []  37.86 250.3 0 top
NOREF#250  -  []  340.83 271.63 0 top
NOREF#251  -  []  236.84 261.06 0 top
NOREF#252  -  []  270.62 247.15 0 top
NOREF#253  -  []  303.09 232.9 0 top
NOREF#254  -  []  220.67 292.95 0 top
NOREF#255  -  []  259.33 196.13 0 top
NOREF#256  -  []  343.95 232.42 90 top
NOREF#257  -  []  345.29 232.02 90 top
NOREF#258  -  []  227.99 181.7 0 top
NOREF#259  -  []  352.05 178.99 0 top
NOREF#260  -  []  352.9 249.57 90 top
NOREF#261  -  []  270.5 243.72 90 top
NOREF#262  -  []  350.59 244.96 0 top
NOREF#263  -  []  392.49 462.53 90 top
NOREF#264  -  []  78.8 277.9 0 top
NOREF#265  -  []  491.48 223.76 0 top
NOREF#266  -  []  475.32 208.21 90 top
NOREF#267  -  []  228.25 233.12 0 top
NOREF#268  -  []  227.41 134.7 0 top
NOREF#269  -  []  382.53 467.08 0 top
NOREF#270  -  []  281.57 134.52 90 top
NOREF#271  -  []  350.5 190.23 90 top
NOREF#272  -  []  229.01 241.77 90 top
NOREF#273  -  []  534.23 206.74 0 top
NOREF#274  -  []  306.33 150.83 0 top
NOREF#275  -  []  263.34 484.08 0 top
NOREF#276  -  []  357.14 144.1 90 top
NOREF#277  -  []  227.95 263.03 0 top
NOREF#278  -  []  267.66 245.09 0 top
NOREF#279  -  []  485.88 158.26 0 top
NOREF#280  -  []  56.85 250.69 0 top
NOREF#281  -  []  472.43 192.01 0 top
NOREF#282  -  []  423.56 417.57 90 top
NOREF#283  -  []  505.61 206.69 90 top
NOREF#284  -  []  539.65 193.24 90 top
NOREF#285  -  []  315.3 250.05 0 top
NOREF#286  -  []  320.04 135.47 90 top
NOREF#287  -  []  460.89 229.42 0 top
NOREF#288  -  []  99.29 157.25 0 top
NOREF#289  -  []  33.48 484.4 0 top
NOREF#290  -  []  50.31 484.4 0 top
NOREF#291  -  []  400.28 484.08 0 top
NOREF#292  -  []  223.95 173.34 90 top
NOREF#293  -  []  273.66 209.1 90 top
NOREF#294  -  []  493.02 240.28 0 top
NOREF#295  -  []  401.38 484.4 0 top
NOREF#296  -  []  48.35 266.27 0 top
NOREF#297  -  []  539.45 192.64 90 top
NOREF#298  -  []  349.25 134 0 top
NOREF#299  -  []  315.19 268.15 90 top
NOREF#300  -  []  343.09 232.9 0 top
NOREF#301  -  []  122.18 236.47 0 top
NOREF#302  -  []  563.28 154.21 90 top
NOREF#303  -  []  39.86 299.18 0 top
NOREF#304  -  []  231.4 181.59 0 top
NOREF#305  -  []  25.36 484.08 0 top
NOREF#306  -  []  225.48 175.27 0 top
NOREF#307  -  []  269.46 145.44 90 top
NOREF#308  -  []  242.43 271.37 90 top
NOREF#309  -  []  227.91 184.41 90 top
NOREF#310  -  []  83.67 289.47 0 top
NOREF#311  -  []  265.94 263.76 0 top
NOREF#312  -  []  335.83 199.63 0 top
NOREF#313  -  []  237.95 143.66 90 top
NOREF#314  -  []  108.69 154.45 0 top
NOREF#315  -  []  87.81 209.07 0 top
NOREF#316  -  []  295.49 254.86 90 top
NOREF#317  -  []  273.08 182.62 90 top
NOREF#318  -  []  226.63 187.43 0 top
NOREF#319  -  []  159.48 484.32 0 top
NOREF#320  -  []  411 483.75 90 top
NOREF#321  -  []  227.65 258.45 90 top
NOREF#322  -  []  350.5 241.77 90 top
NOREF#323  -  []  270.26 184.4 0 top
NOREF#324  -  []  309.23 268.44 0 top
NOREF#325  -  []  333.86 192.91 90 top
NOREF#326  -  []  307.67 484.08 0 top
NOREF#327  -  []  255.09 261.99 90 top
NOREF#328  -  []  343.09 233.82 0 top
NOREF#329  -  []  312.8 187.32 90 top
NOREF#330  -  []  135.09 483.84 90 top
NOREF#331  -  []  230.75 250.05 0 top
NOREF#332  -  []  311.08 269.73 0 top
NOREF#333  -  []  331.16 251.72 0 top
NOREF#334  -  []  226.54 134.31 90 top
NOREF#335  -  []  271.27 239.68 90 top
NOREF#336  -  []  122.18 138.68 0 top
NOREF#337  -  []  271.81 181.77 90 top
NOREF#338  -  []  263.09 174.38 0 top
NOREF#339  -  []  330.12 484.08 0 top
NOREF#340  -  []  304.09 172.66 0 top
NOREF#341  -  []  39.09 484.4 0 top
NOREF#342  -  []  274.44 138.77 0 top
NOREF#343  -  []  348.62 245.61 0 top
NOREF#344  -  []  418.95 463.08 90 top
NOREF#345  -  []  498.43 231.86 90 top
NOREF#346  -  []  257.43 484.4 0 top
NOREF#347  -  []  245.1 484.08 0 top
NOREF#348  -  []  301.84 204.24 0 top
NOREF#349  -  []  46.4 484.08 0 top
NOREF#350  -  []  258.84 484.4 0 top
NOREF#351  -  []  111.42 191.22 0 top
NOREF#352  -  []  522.13 150.36 0 top
NOREF#353  -  []  333.29 253.86 90 top
NOREF#354  -  []  91.44 302.01 0 top
NOREF#355  -  []  229.11 232.64 90 top
NOREF#356  -  []  335.71 182 0 top
NOREF#357  -  []  273.08 242.62 90 top
NOREF#358  -  []  310.82 180.82 90 top
NOREF#359  -  []  311.08 209.73 0 top
NOREF#360  -  []  491.48 192.01 0 top
NOREF#361  -  []  311.89 244.88 90 top
NOREF#362  -  []  215.16 179.65 90 top
NOREF#363  -  []  306.63 187.43 0 top
NOREF#364  -  []  192.71 286.85 0 top
NOREF#365  -  []  112.47 126.77 90 top
NOREF#366  -  []  408.7 462.53 90 top
NOREF#367  -  []  473.2 133.68 90 top
NOREF#368  -  []  158.26 484.08 0 top
NOREF#369  -  []  122.18 233.93 0 top
NOREF#370  -  []  295.09 206.49 0 top
NOREF#371  -  []  295.16 251.22 90 top
NOREF#372  -  []  347.05 134.08 90 top
NOREF#373  -  []  274.07 483.75 90 top
NOREF#374  -  []  227.75 232.44 90 top
NOREF#375  -  []  475.38 190.01 0 top
NOREF#376  -  []  362.39 484.08 0 top
NOREF#377  -  []  241.96 270.25 0 top
NOREF#378  -  []  355.19 208.15 90 top
NOREF#379  -  []  249.83 165.63 90 top
NOREF#380  -  []  29.06 483.76 90 top
NOREF#381  -  []  490.86 231.38 90 top
NOREF#382  -  []  231.26 187.56 0 top
NOREF#383  -  []  352.05 241.59 0 top
NOREF#384  -  []  542.83 150.57 0 top
NOREF#385  -  []  340.81 235.6 90 top
NOREF#386  -  []  485.13 223.76 0 top
NOREF#387  -  []  408.75 462.48 90 top
NOREF#388  -  []  458.37 199.87 90 top
NOREF#389  -  []  313.66 209.1 90 top
NOREF#390  -  []  212.45 250.39 0 top
NOREF#391  -  []  105.64 157.25 0 top
NOREF#392  -  []  213.09 243.29 90 top
NOREF#393  -  []  306.63 247.43 0 top
NOREF#394  -  []  236.39 484.4 0 top
NOREF#395  -  []  224.09 172.66 0 top
NOREF#396  -  []  271.6 181.11 90 top
NOREF#397  -  []  128 484.08 0 top
NOREF#398  -  []  215.49 183.29 90 top
NOREF#399  -  []  475.32 142.17 90 top
NOREF#400  -  []  210.61 247.17 90 top
NOREF#401  -  []  272.57 244.23 90 top
NOREF#402  -  []  227.25 173.9 90 top
NOREF#403  -  []  225.05 145.8 90 top
NOREF#404  -  []  458.75 172.72 0 top
NOREF#405  -  []  224.52 285.16 90 top
NOREF#406  -  []  128.68 483.84 90 top
NOREF#407  -  []  24.85 483.76 90 top
NOREF#408  -  []  243.2 483.75 90 top
NOREF#409  -  []  365.64 136.62 90 top
NOREF#410  -  []  350.62 245.85 0 top
NOREF#411  -  []  115.04 249.7 0 top
NOREF#412  -  []  101.59 188.2 0 top
NOREF#413  -  []  265.05 146.58 0 top
NOREF#414  -  []  350.62 187.15 0 top
NOREF#415  -  []  115.19 484.32 0 top
NOREF#416  -  []  213.99 193.86 90 top
NOREF#417  -  []  344.52 293.03 90 top
NOREF#418  -  []  540.03 220.67 0 top
NOREF#419  -  []  286.63 484.08 0 top
NOREF#420  -  []  306.74 298.45 0 top
NOREF#421  -  []  369.83 165.63 90 top
NOREF#422  -  []  334.36 241.55 0 top
NOREF#423  -  []  475.18 160.91 90 top
NOREF#424  -  []  451.08 256.31 0 top
NOREF#425  -  []  246.21 484.4 0 top
NOREF#426  -  []  47.3 483.76 90 top
NOREF#427  -  []  340.62 297.29 0 top
NOREF#428  -  []  480.26 147.38 0 top
NOREF#429  -  []  349.31 462.48 90 top
NOREF#430  -  []  249.83 203.63 90 top
NOREF#431  -  []  304.41 231.76 90 top
NOREF#432  -  []  294.81 192.91 90 top
NOREF#433  -  []  271.89 184.96 0 top
NOREF#434  -  []  352.7 250.05 0 top
NOREF#435  -  []  268.67 241.29 0 top
NOREF#436  -  []  95.99 217.95 0 top
NOREF#437  -  []  154.91 290.38 90 top
NOREF#438  -  []  335.51 241.35 90 top
NOREF#439  -  []  313.43 186.02 90 top
NOREF#440  -  []  269.25 134 0 top
NOREF#441  -  []  36.28 484.4 0 top
NOREF#442  -  []  232.2 286.98 90 top
NOREF#443  -  []  456.33 253.51 0 top
NOREF#444  -  []  103.28 236.8 0 top
NOREF#445  -  []  541.95 196.24 90 top
NOREF#446  -  []  546.77 170.72 90 top
NOREF#447  -  []  251.16 176.15 90 top
NOREF#448  -  []  498.43 213.47 90 top
NOREF#449  -  []  462.68 190.01 0 top
NOREF#450  -  []  315.44 254.76 90 top
NOREF#451  -  []  485.13 192.01 0 top
NOREF#452  -  []  344.91 173.9 0 top
NOREF#453  -  []  83.2 262.88 90 top
NOREF#454  -  []  41.26 273.28 0 top
NOREF#455  -  []  227.67 185.09 0 top
NOREF#456  -  []  272.22 183.1 0 top
NOREF#457  -  []  466.08 223.76 0 top
NOREF#458  -  []  267.9 242.43 90 top
NOREF#459  -  []  230.26 244.4 0 top
NOREF#460  -  []  232.26 245.64 90 top
NOREF#461  -  []  87.81 227.81 0 top
NOREF#462  -  []  262.84 483.75 90 top
NOREF#463  -  []  252.33 242.3 90 top
NOREF#464  -  []  349.94 186.91 0 top
NOREF#465  -  []  42.06 297.73 90 top
NOREF#466  -  []  549.06 211.81 90 top
NOREF#467  -  []  479.53 253.51 0 top
NOREF#468  -  []  48.53 248.1 0 top
NOREF#469  -  []  81.69 261.04 90 top
NOREF#470  -  []  344.52 287.7 90 top
NOREF#471  -  []  392.79 467.63 0 top
NOREF#472  -  []  371.13 467.68 0 top
NOREF#473  -  []  354.48 242.93 90 top
NOREF#474  -  []  334.66 241.23 0 top
NOREF#475  -  []  116.29 151.25 90 top
NOREF#476  -  []  476.48 256.31 0 top
NOREF#477  -  []  229.28 241.06 0 top
NOREF#478  -  []  301.76 484.4 0 top
NOREF#479  -  []  213.1 191.59 0 top
NOREF#480  -  []  359.59 140.38 90 top
NOREF#481  -  []  56.67 268.86 0 top
NOREF#482  -  []  212.33 182.3 90 top
NOREF#483  -  []  347.05 134.86 0 top
NOREF#484  -  []  82.32 289.93 90 top
NOREF#485  -  []  253.99 242.3 90 top
NOREF#486  -  []  548.24 221.6 0 top
NOREF#487  -  []  41.89 484.4 0 top
NOREF#488  -  []  40.49 484.4 0 top
NOREF#489  -  []  503.71 209.84 0 top
NOREF#490  -  []  272.22 243.1 0 top
NOREF#491  -  []  306.71 185.85 0 top
NOREF#492  -  []  226.54 134.08 0 top
NOREF#493  -  []  480.26 137.53 90 top
NOREF#494  -  []  483.31 225.83 90 top
NOREF#495  -  []  352.91 178.51 90 top
NOREF#496  -  []  275.23 163.88 90 top
NOREF#497  -  []  303.95 173.9 90 top
NOREF#498  -  []  355.81 182.28 90 top
NOREF#499  -  []  396.07 484.08 0 top
NOREF#500  -  []  351.6 249.57 90 top
NOREF#501  -  []  331.96 253.56 0 top
NOREF#502  -  []  238.71 140.12 90 top
NOREF#503  -  []  466.83 253.51 0 top
NOREF#504  -  []  334.66 252.79 0 top
NOREF#505  -  []  547.34 238.42 0 top
NOREF#506  -  []  353.98 484.08 0 top
NOREF#507  -  []  267.56 144.79 90 top
NOREF#508  -  []  294.75 484.4 0 top
NOREF#509  -  []  312.21 244.43 0 top
NOREF#510  -  []  273.08 240.67 90 top
NOREF#511  -  []  320.04 137.42 90 top
NOREF#512  -  []  307.99 241.05 0 top
NOREF#513  -  []  224.42 176.56 0 top
NOREF#514  -  []  252.54 182.65 90 top
NOREF#515  -  []  309 241.77 90 top
NOREF#516  -  []  344.91 233.9 0 top
NOREF#517  -  []  273.73 243.95 90 top
NOREF#518  -  []  478.69 134.36 90 top
NOREF#519  -  []  347.25 234.3 90 top
NOREF#520  -  []  324.01 483.75 90 top
NOREF#521  -  []  250.72 484.08 0 top
NOREF#522  -  []  92.94 189 0 top
NOREF#523  -  []  332.93 484.08 0 top
NOREF#524  -  []  294.66 252.79 0 top
NOREF#525  -  []  483.31 194.08 90 top
NOREF#526  -  []  236.61 287.27 90 top
NOREF#527  -  []  347.41 133.69 0 top
NOREF#528  -  []  122.64 183 90 top
NOREF#529  -  []  570 165.52 90 top
NOREF#530  -  []  535.51 219.1 90 top
NOREF#531  -  []  58.25 268.08 90 top
NOREF#532  -  []  97.99 252.35 90 top
NOREF#533  -  []  229.23 208.44 0 top
NOREF#534  -  []  232.35 284.59 90 top
NOREF#535  -  []  504.91 227.35 90 top
NOREF#536  -  []  369.83 162.63 90 top
NOREF#537  -  []  270.59 244.96 0 top
NOREF#538  -  []  490.86 136.13 90 top
NOREF#539  -  []  268.03 289.54 0 top
NOREF#540  -  []  213.99 182.3 90 top
NOREF#541  -  []  274.57 484.08 0 top
NOREF#542  -  []  229.86 184.37 90 top
NOREF#543  -  []  226.03 185.61 0 top
NOREF#544  -  []  456.39 210.9 90 top
NOREF#545  -  []  255.38 253.86 90 top
NOREF#546  -  []  344.42 176.56 0 top
NOREF#547  -  []  196.37 286.37 90 top
NOREF#548  -  []  295.71 253.56 0 top
NOREF#549  -  []  318.57 231.63 90 top
NOREF#550  -  []  270.87 210.03 90 top
NOREF#551  -  []  300.81 187.17 90 top
NOREF#552  -  []  272.22 241.15 0 top
NOREF#553  -  []  352.2 286.98 90 top
NOREF#554  -  []  253.22 484.4 0 top
NOREF#555  -  []  273.11 183.76 90 top
NOREF#556  -  []  92.94 220.75 0 top
NOREF#557  -  []  396.97 483.75 90 top
NOREF#558  -  []  224.48 260.94 90 top
NOREF#559  -  []  102.38 172.97 0 top
NOREF#560  -  []  294.36 253.12 0 top
NOREF#561  -  []  228.67 241.94 0 top
NOREF#562  -  []  291.16 187.72 90 top
NOREF#563  -  []  352.86 184.43 0 top
NOREF#564  -  []  110.89 154.45 0 top
NOREF#565  -  []  469.03 253.51 0 top
NOREF#566  -  []  471.23 253.51 0 top
NOREF#567  -  []  451.08 224.56 0 top
NOREF#568  -  []  335.38 253.86 90 top
NOREF#569  -  []  224.91 233.9 0 top
NOREF#570  -  []  468.6 137.92 0 top
NOREF#571  -  []  254.66 181.23 0 top
NOREF#572  -  []  269.3 245.85 0 top
NOREF#573  -  []  230.16 184.72 90 top
NOREF#574  -  []  338.17 209.61 90 top
NOREF#575  -  []  331.53 484.08 0 top
NOREF#576  -  []  311.81 181.77 90 top
NOREF#577  -  []  354.97 467.63 0 top
NOREF#578  -  []  294.29 255.5 0 top
NOREF#579  -  []  228.44 202.36 0 top
NOREF#580  -  []  478.69 229.61 90 top
NOREF#581  -  []  473.22 205.99 0 top
NOREF#582  -  []  214.68 182.3 90 top
NOREF#583  -  []  546.96 209.34 0 top
NOREF#584  -  []  354.61 299.77 0 top
NOREF#585  -  []  347.66 185.09 0 top
NOREF#586  -  []  99.29 220.75 0 top
NOREF#587  -  []  352.57 244.23 90 top
NOREF#588  -  []  260.67 292.95 0 top
NOREF#589  -  []  297.85 484.08 0 top
NOREF#590  -  []  229.86 244.37 90 top
NOREF#591  -  []  273.63 143.53 0 top
NOREF#592  -  []  213.09 243.93 0 top
NOREF#593  -  []  272.91 241.11 90 top
NOREF#594  -  []  229.3 185.2 0 top
NOREF#595  -  []  294.29 243.93 0 top
NOREF#596  -  []  255.49 183.29 90 top
NOREF#597  -  []  231.71 184.72 0 top
NOREF#598  -  []  216.21 181.35 90 top
NOREF#599  -  []  375.02 484.08 0 top
NOREF#600  -  []  300.83 211.63 0 top
NOREF#601  -  []  504.01 228.32 0 top
NOREF#602  -  []  351.88 244.88 90 top
NOREF#603  -  []  303.27 174.06 0 top
NOREF#604  -  []  409.55 467.08 0 top
NOREF#605  -  []  260.24 484.4 0 top
NOREF#606  -  []  534.23 205.35 0 top
NOREF#607  -  []  226.91 146.64 0 top
NOREF#608  -  []  311.89 244.96 0 top
NOREF#609  -  []  300.96 187.12 90 top
NOREF#610  -  []  468.26 138.4 0 top
NOREF#611  -  []  103.59 151.25 90 top
NOREF#612  -  []  477.58 221.76 0 top
NOREF#613  -  []  301.62 297 90 top
NOREF#614  -  []  225.33 134.7 0 top
NOREF#615  -  []  331.23 176.59 90 top
NOREF#616  -  []  305.88 235.27 0 top
NOREF#617  -  []  78.8 290.36 0 top
NOREF#618  -  []  340.96 187.12 90 top
NOREF#619  -  []  560.49 154.6 0 top
NOREF#620  -  []  346.45 147.01 90 top
NOREF#621  -  []  315.33 293.17 0 top
NOREF#622  -  []  480.78 186.81 90 top
NOREF#623  -  []  310.62 185.85 0 top
NOREF#624  -  []  349.52 467.68 0 top
NOREF#625  -  []  87.91 170.18 90 top
NOREF#626  -  []  333.1 240.02 0 top
NOREF#627  -  []  505.85 211.79 0 top
NOREF#628  -  []  226.54 133.3 90 top
NOREF#629  -  []  108.69 249.7 0 top
NOREF#630  -  []  291.16 180.15 0 top
NOREF#631  -  []  283.96 287.7 90 top
NOREF#632  -  []  278.39 141.02 0 top
NOREF#633  -  []  473.22 176.78 0 top
NOREF#634  -  []  274.61 298.99 90 top
NOREF#635  -  []  301.62 292.95 90 top
NOREF#636  -  []  213.66 254.76 0 top
NOREF#637  -  []  387.15 483.75 90 top
NOREF#638  -  []  311.16 241.77 90 top
NOREF#639  -  []  292.78 179.12 90 top
NOREF#640  -  []  235.33 293.17 0 top
NOREF#641  -  []  476.48 224.56 0 top
NOREF#642  -  []  104.54 217.95 0 top
NOREF#643  -  []  279.73 246.59 0 top
NOREF#644  -  []  568.79 166.69 0 top
NOREF#645  -  []  264.09 232.66 0 top
NOREF#646  -  []  268.44 202.36 0 top
NOREF#647  -  []  85.83 143.59 90 top
NOREF#648  -  []  100.39 217.95 0 top
NOREF#649  -  []  81.82 265.27 0 top
NOREF#650  -  []  233.11 183.76 90 top
NOREF#651  -  []  456.13 192.66 90 top
NOREF#652  -  []  558.12 164.49 0 top
NOREF#653  -  []  309.53 181.46 90 top
NOREF#654  -  []  348.25 174.12 0 top
NOREF#655  -  []  37.68 266.27 0 top
NOREF#656  -  []  306.45 147.01 90 top
NOREF#657  -  []  310.74 190.05 0 top
NOREF#658  -  []  540.94 220.27 90 top
NOREF#659  -  []  336.91 252.91 90 top
NOREF#660  -  []  269.5 210 0 top
NOREF#661  -  []  39.07 250.69 0 top
NOREF#662  -  []  234.23 247.83 0 top
NOREF#663  -  []  549.06 207.62 90 top
NOREF#664  -  []  264.96 136.11 90 top
NOREF#665  -  []  230.01 210.51 0 top
NOREF#666  -  []  348.67 241.29 0 top
NOREF#667  -  []  125.19 484.08 0 top
NOREF#668  -  []  401.68 484.08 0 top
NOREF#669  -  []  295.76 180.75 0 top
NOREF#670  -  []  334.29 183.93 0 top
NOREF#671  -  []  20.85 484.4 0 top
NOREF#672  -  []  105.64 220.75 0 top
NOREF#673  -  []  302.06 484.08 0 top
NOREF#674  -  []  34.68 483.76 90 top
NOREF#675  -  []  43.02 254.33 90 top
NOREF#676  -  []  320.37 135.17 0 top
NOREF#677  -  []  265.48 233.73 90 top
NOREF#678  -  []  295.51 181.35 90 top
NOREF#679  -  []  273.43 186.02 90 top
NOREF#680  -  []  215.51 181.35 90 top
NOREF#681  -  []  350.87 484.4 0 top
NOREF#682  -  []  119.4 484.32 0 top
NOREF#683  -  []  311.4 186.13 0 top
NOREF#684  -  []  353.34 250.05 0 top
NOREF#685  -  []  482.83 192.81 0 top
NOREF#686  -  []  303.95 233.34 90 top
NOREF#687  -  []  314.75 285.63 90 top
NOREF#688  -  []  549.91 171.11 0 top
NOREF#689  -  []  306.6 190.23 90 top
NOREF#690  -  []  333.61 253.56 0 top
NOREF#691  -  []  346.84 250.05 0 top
NOREF#692  -  []  263.95 232.42 90 top
NOREF#693  -  []  233.4 298.37 0 top
NOREF#694  -  []  328.22 483.75 90 top
NOREF#695  -  []  270.01 210.51 0 top
NOREF#696  -  []  292.24 484.08 0 top
NOREF#697  -  []  551.91 164.1 0 top
NOREF#698  -  []  480.78 155.06 90 top
NOREF#699  -  []  549.44 220.95 90 top
NOREF#700  -  []  197.15 287.03 90 top
NOREF#701  -  []  493.02 174.24 0 top
NOREF#702  -  []  487.59 169.38 90 top
NOREF#703  -  []  343.27 233.14 0 top
NOREF#704  -  []  277.11 164.14 90 top
NOREF#705  -  []  113.09 217.95 0 top
NOREF#706  -  []  267.71 189.57 90 top
NOREF#707  -  []  268.55 178.53 90 top
NOREF#708  -  []  335.16 251.22 90 top
NOREF#709  -  []  243.7 484.08 0 top
NOREF#710  -  []  540.94 233.23 0 top
NOREF#711  -  []  306.03 185.61 0 top
NOREF#712  -  []  156.13 483.84 90 top
NOREF#713  -  []  98.19 249.7 0 top
NOREF#714  -  []  275.12 300.55 0 top
NOREF#715  -  []  160.34 483.84 90 top
NOREF#716  -  []  272.87 484.4 0 top
NOREF#717  -  []  295.16 239.65 90 top
NOREF#718  -  []  223.27 174.62 0 top
NOREF#719  -  []  111.99 252.5 0 top
NOREF#720  -  []  362.33 233.13 90 top
NOREF#721  -  []  336.91 241.35 90 top
NOREF#722  -  []  271.4 186.13 0 top
NOREF#723  -  []  224.41 171.76 90 top
NOREF#724  -  []  273.63 243.41 0 top
NOREF#725  -  []  270.36 484.08 0 top
NOREF#726  -  []  270.59 184.96 0 top
NOREF#727  -  []  566.06 170.72 0 top
NOREF#728  -  []  351.12 183.92 90 top
NOREF#729  -  []  351.71 184.72 0 top
NOREF#730  -  []  303.95 232.42 90 top
NOREF#731  -  []  493.48 186.81 90 top
NOREF#732  -  []  87.91 201.93 90 top
NOREF#733  -  []  226.63 247.43 0 top
NOREF#734  -  []  22.05 483.76 90 top
NOREF#735  -  []  244.17 272.99 0 top
NOREF#736  -  []  117.24 154.45 0 top
NOREF#737  -  []  87.91 200.66 0 top
NOREF#738  -  []  347.25 173.9 90 top
NOREF#739  -  []  353.07 182.62 90 top
NOREF#740  -  []  108.69 217.95 0 top
NOREF#741  -  []  293.86 181.35 90 top
NOREF#742  -  []  347.25 233.9 90 top
NOREF#743  -  []  87.69 154.45 0 top
NOREF#744  -  []  211.64 195.18 0 top
NOREF#745  -  []  271.26 187.56 0 top
NOREF#746  -  []  274.97 145.37 90 top
NOREF#747  -  []  234.1 286.98 90 top
NOREF#748  -  []  255.49 243.29 90 top
NOREF#749  -  []  102.38 170.43 0 top
NOREF#750  -  []  231.61 189.57 90 top
NOREF#751  -  []  156.86 484.08 0 top
NOREF#752  -  []  547.86 196.96 0 top
NOREF#753  -  []  273.73 183.95 90 top
NOREF#754  -  []  268.62 245.61 0 top
NOREF#755  -  []  293.1 240.02 0 top
NOREF#756  -  []  294.29 195.5 0 top
NOREF#757  -  []  347.05 135.09 90 top
NOREF#758  -  []  235.12 299.54 0 top
NOREF#759  -  []  370.32 463.08 90 top
NOREF#760  -  []  255.01 242 0 top
NOREF#761  -  []  312.45 243.75 90 top
NOREF#762  -  []  454.13 190.01 0 top
NOREF#763  -  []  235.21 285.21 90 top
NOREF#764  -  []  333.39 255.18 0 top
NOREF#765  -  []  66.13 266.27 0 top
NOREF#766  -  []  253.99 253.86 90 top
NOREF#767  -  []  304.91 173.9 0 top
NOREF#768  -  []  264.41 231.76 90 top
NOREF#769  -  []  233.02 254.4 0 top
NOREF#770  -  []  214.36 254.76 0 top
NOREF#771  -  []  314.82 284.84 90 top
NOREF#772  -  []  342.95 290.44 90 top
NOREF#773  -  []  211.34 194.86 0 top
NOREF#774  -  []  262.45 171.5 0 top
NOREF#775  -  []  539.65 207.34 90 top
NOREF#776  -  []  309.11 172.64 90 top
